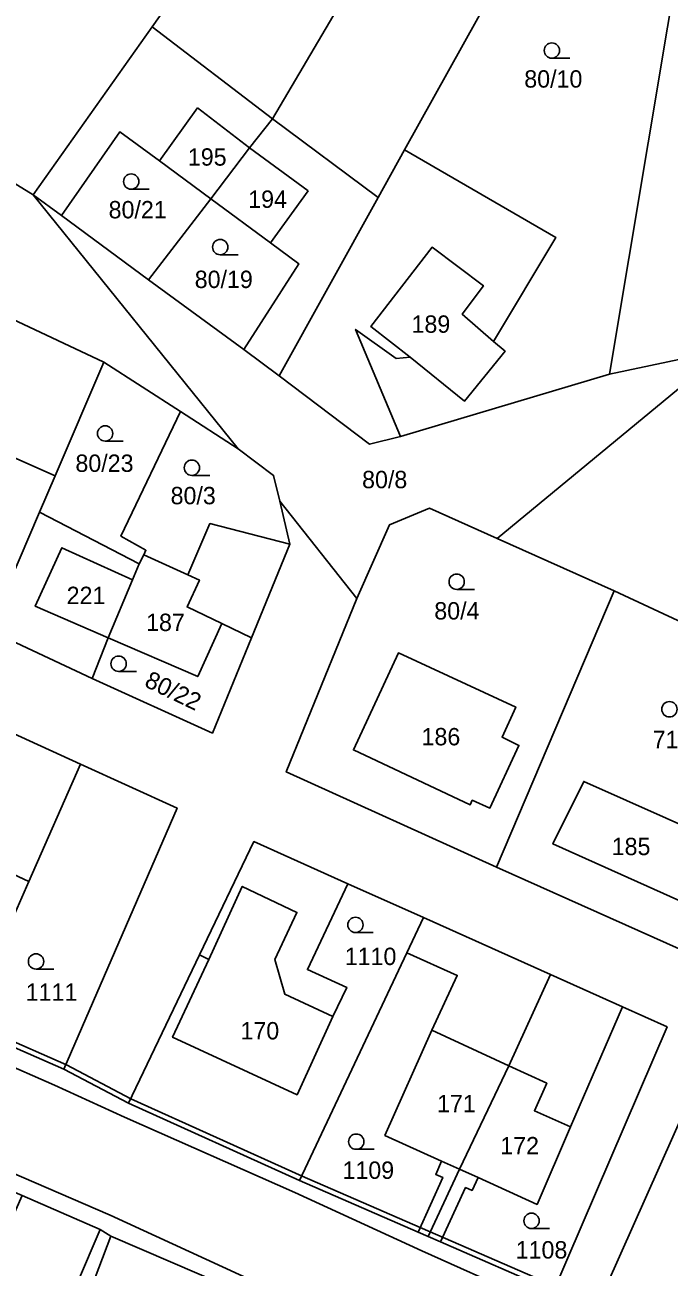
# Model space of a CAD drawing. Extents: x -654083 to -650132, y -1099819 to -1096699.
# Drawn here: x -652413.7 to -652350.7, y -1097932.6 to -1097811 of the extents above; entities that cross this region are included whole.
import ezdxf

# ---------------------------------------------------------------- set-up
doc = ezdxf.new("R2010")
doc.units = 0
for name, color, linetype in [('Hranice - vnitř_ kresba', 7, 'Continuous'), ('Obvody jako plochy', 7, 'Continuous'), ('Ostatní hranice', 7, 'Continuous'), ('Parcelní čísla', 7, 'Continuous'), ('Značky kultur', 7, 'Continuous')]:
    doc.layers.add(name, color=color, linetype=linetype)

msp = doc.modelspace()

# ---------------------------------------------------------------- linework, layer by layer
at = {"layer": 'Hranice - vnitř_ kresba'}
for p, q in [((-652396.84, -1097819.15), (-652400.56, -1097824.34)), ((-652396.84, -1097819.15), (-652391.74, -1097823.07)), ((-652391.74, -1097823.07), (-652385.99, -1097827.27)), ((-652385.99, -1097827.27), (-652389.69, -1097832.37)), ((-652379.85, -1097840.57), (-652373.87, -1097832.79)), ((-652373.87, -1097832.79), (-652368.84, -1097836.57)), ((-652368.84, -1097836.57), (-652370.92, -1097839.35)), ((-652367.85, -1097842.01), (-652370.92, -1097839.35)), ((-652379.85, -1097840.57), (-652376.02, -1097843.57)), ((-652410.12, -1097862.22), (-652412.72, -1097867.95)), ((-652403.2, -1097865.36), (-652410.12, -1097862.22)), ((-652397.78, -1097864.87), (-652396.65, -1097865.38)), ((-652397.86, -1097868.01), (-652396.65, -1097865.38)), ((-652405.57, -1097871.02), (-652412.72, -1097867.95)), ((-652394.46, -1097869.62), (-652397.86, -1097868.01)), ((-652484.26, -1097882.64), (-652410.83, -1097914.82)), ((-652420.25, -1097891.7), (-652413.35, -1097894.89)), ((-652395.73, -1097902.54), (-652392.46, -1097895.37)), ((-652392.46, -1097895.37), (-652387.1, -1097897.91)), ((-652387.1, -1097897.91), (-652389.26, -1097902.54)), ((-652389.26, -1097902.54), (-652388.3, -1097905.93)), ((-652456.16, -1097905.72), (-652405.39, -1097927.55)), ((-652383.59, -1097908.1), (-652388.3, -1097905.93)), ((-652373.9, -1097909.44), (-652366.35, -1097912.94)), ((-652366.35, -1097912.94), (-652362.64, -1097914.64)), ((-652410.83, -1097914.82), (-652404, -1097917.96)), ((-652362.64, -1097914.64), (-652363.85, -1097917.34)), ((-652404, -1097917.96), (-652387.32, -1097925.33)), ((-652363.85, -1097917.34), (-652360.31, -1097918.91)), ((-652372.96, -1097922.26), (-652371.17, -1097923.05)), ((-652371.17, -1097923.05), (-652369.36, -1097923.86)), ((-652387.32, -1097925.33), (-652374.88, -1097931.06)), ((-652405.39, -1097927.55), (-652368.53, -1097944.47)), ((-652374.88, -1097931.06), (-652362.67, -1097936.49))]:
    msp.add_line(p, q, dxfattribs=at)
at = {"layer": 'Obvody jako plochy'}
for points in [[(-652839.76, -1097733.97), (-652826.6, -1097739.44), (-652822.57, -1097741.08), (-652707.93, -1097793.49), (-652704.24, -1097795.08), (-652617.25, -1097835.71), (-652588.75, -1097848.74), (-652581.26, -1097852.35), (-652575.63, -1097854.85), (-652550.17, -1097866.18), (-652501.51, -1097887.82), (-652496.71, -1097889.3), (-652483.12, -1097895.45), (-652482.5, -1097895.73), (-652456.7, -1097907.4), (-652446.55, -1097911.8), (-652439.64, -1097914.73), (-652414, -1097925.64), (-652406.37, -1097928.95), (-652405.33, -1097929.6), (-652381.94, -1097939.67)], [(-652259.95, -1097978.53), (-652289.58, -1097967.54), (-652304.17, -1097961.16), (-652306.89, -1097960.07), (-652358.06, -1097937.32), (-652361.99, -1097934.98), (-652373.04, -1097930.17), (-652374.25, -1097929.65), (-652375.24, -1097929.22), (-652386.86, -1097924.16), (-652403.6, -1097916.6), (-652409.91, -1097913.27), (-652436.78, -1097901.48), (-652463.96, -1097889.56), (-652483.6, -1097880.94), (-652534, -1097858.11), (-652537.59, -1097856.5), (-652554.49, -1097848.9), (-652581.83, -1097835.42), (-652676.84, -1097793.83), (-652695.77, -1097785.5), (-652811.07, -1097733.73)], [(-652500.72, -1097835.3), (-652484.26, -1097848.66), (-652475.91, -1097843.07), (-652447.26, -1097856.27), (-652431.98, -1097863.57), (-652417.27, -1097870.27), (-652407.16, -1097875.02), (-652395.37, -1097880.36), (-652391.55, -1097871.03), (-652387.8, -1097861.86), (-652388.79, -1097857.67), (-652381.25, -1097867.2), (-652388.15, -1097884.17), (-652367.56, -1097893.5), (-652346.61, -1097902.85)], [(-652334.39, -1097876.52), (-652356.03, -1097866.43), (-652367.48, -1097861.3), (-652345.07, -1097842.82)], [(-652361.99, -1097934.98), (-652350.86, -1097909.12), (-652355.23, -1097907.16), (-652362.28, -1097904), (-652374.72, -1097898.42), (-652382.11, -1097895.11), (-652391.32, -1097890.98), (-652396.64, -1097902.08), (-652403.6, -1097916.6), (-652409.91, -1097913.27), (-652398.84, -1097887.71), (-652408.29, -1097883.4), (-652415.21, -1097880.24), (-652420.04, -1097878.04), (-652425.5, -1097875.55), (-652439.82, -1097869.02), (-652453.31, -1097862.91), (-652458.02, -1097860.78), (-652472.61, -1097854.18), (-652477.46, -1097866.14), (-652483.6, -1097880.94), (-652534, -1097858.11)], [(-652346.41, -1097911.18), (-652358.06, -1097937.32)]]:
    msp.add_lwpolyline(points, dxfattribs=at)
for points in [[(-652379.48, -1097780.45), (-652401.26, -1097811.21), (-652412.92, -1097827.67), (-652420.53, -1097823), (-652433.6, -1097806.15), (-652430.36, -1097800.91), (-652417.6, -1097810.84), (-652413.9, -1097806.33), (-652416.04, -1097804.59), (-652414.87, -1097802.5), (-652417.21, -1097800.53), (-652415.53, -1097798.38), (-652418.34, -1097796.15), (-652417.34, -1097794.99), (-652420.39, -1097792.61), (-652419.7, -1097791.77), (-652421.1, -1097790.74), (-652426.06, -1097786.86), (-652405.32, -1097768.69), (-652381.57, -1097778.69)], [(-652370.5, -1097787.99), (-652389.49, -1097820.24), (-652401.26, -1097811.21), (-652379.48, -1097780.45)], [(-652376.56, -1097823.27), (-652360.94, -1097795.15), (-652370.5, -1097787.99), (-652389.49, -1097820.24), (-652379.15, -1097827.93)], [(-652348.92, -1097799.91), (-652356.49, -1097845.22), (-652376.96, -1097851.32), (-652381.36, -1097840.85), (-652377.38, -1097843.7), (-652376.02, -1097843.57), (-652370.69, -1097847.86), (-652366.72, -1097842.98), (-652367.85, -1097842.01), (-652361.76, -1097831.84), (-652376.56, -1097823.27), (-652360.94, -1097795.15)], [(-652345.07, -1097842.82), (-652333.27, -1097839.84), (-652323.69, -1097812.92), (-652334.65, -1097806.31), (-652348.92, -1097799.91), (-652356.49, -1097845.22)], [(-652398.51, -1097848.89), (-652406, -1097844.06), (-652419.57, -1097837.69), (-652435.51, -1097803.7), (-652433.6, -1097806.15), (-652420.53, -1097823), (-652412.92, -1097827.67), (-652392.87, -1097852.52)], [(-652389.49, -1097820.24), (-652401.26, -1097811.21), (-652412.92, -1097827.67), (-652410.15, -1097829.7), (-652404.43, -1097821.49), (-652400.56, -1097824.34), (-652395.54, -1097828.05), (-652391.74, -1097823.07)], [(-652396.84, -1097819.15), (-652391.74, -1097823.07), (-652395.54, -1097828.05), (-652400.56, -1097824.34)], [(-652389.49, -1097820.24), (-652379.15, -1097827.93), (-652388.83, -1097845.37), (-652392.3, -1097842.8), (-652386.93, -1097834.41), (-652389.69, -1097832.37), (-652395.54, -1097828.05), (-652391.74, -1097823.07)], [(-652400.56, -1097824.34), (-652404.43, -1097821.49), (-652410.15, -1097829.7), (-652401.62, -1097835.99), (-652395.54, -1097828.05)], [(-652385.99, -1097827.27), (-652389.69, -1097832.37), (-652395.54, -1097828.05), (-652391.74, -1097823.07)], [(-652370.69, -1097847.86), (-652366.72, -1097842.98), (-652367.85, -1097842.01), (-652361.76, -1097831.84), (-652376.56, -1097823.27), (-652379.15, -1097827.93), (-652388.83, -1097845.37), (-652380.01, -1097852.09), (-652376.96, -1097851.32), (-652381.36, -1097840.85), (-652377.38, -1097843.7), (-652376.02, -1097843.57)], [(-652378.03, -1097859.96), (-652381.25, -1097867.2), (-652388.79, -1097857.67), (-652389.39, -1097855.14), (-652392.87, -1097852.52), (-652412.92, -1097827.67), (-652410.15, -1097829.7), (-652401.62, -1097835.99), (-652392.3, -1097842.8), (-652388.83, -1097845.37), (-652380.01, -1097852.09), (-652376.96, -1097851.32), (-652356.49, -1097845.22), (-652345.07, -1097842.82), (-652367.48, -1097861.3), (-652374.12, -1097858.33)], [(-652389.69, -1097832.37), (-652386.93, -1097834.41), (-652392.3, -1097842.8), (-652401.62, -1097835.99), (-652395.54, -1097828.05)], [(-652376.02, -1097843.57), (-652370.69, -1097847.86), (-652366.72, -1097842.98), (-652367.85, -1097842.01), (-652370.92, -1097839.35), (-652368.84, -1097836.57), (-652373.87, -1097832.79), (-652379.85, -1097840.57)], [(-652410.79, -1097855.19), (-652406, -1097844.06), (-652419.57, -1097837.69), (-652421.32, -1097836.9), (-652429.03, -1097841.42), (-652432.79, -1097850.39), (-652435.71, -1097857.37), (-652430.1, -1097859.83), (-652421.88, -1097863.51), (-652416.92, -1097852.46)], [(-652402.1, -1097862.91), (-652402.54, -1097863.79), (-652412.32, -1097858.74), (-652410.79, -1097855.19), (-652406, -1097844.06), (-652398.51, -1097848.89), (-652404.33, -1097861.08), (-652401.88, -1097862.46)], [(-652388.79, -1097857.67), (-652387.8, -1097861.86), (-652395.62, -1097859.85), (-652397.78, -1097864.87), (-652402.1, -1097862.91), (-652401.88, -1097862.46), (-652404.33, -1097861.08), (-652398.51, -1097848.89), (-652392.87, -1097852.52), (-652389.39, -1097855.14)], [(-652412.32, -1097858.74), (-652410.79, -1097855.19), (-652416.92, -1097852.46), (-652421.88, -1097863.51), (-652430.1, -1097859.83), (-652431.98, -1097863.57), (-652417.27, -1097870.27)], [(-652407.16, -1097875.02), (-652405.57, -1097871.02), (-652403.2, -1097865.36), (-652402.54, -1097863.79), (-652412.32, -1097858.74), (-652417.27, -1097870.27)], [(-652356.03, -1097866.43), (-652367.48, -1097861.3), (-652374.12, -1097858.33), (-652378.03, -1097859.96), (-652381.25, -1097867.2), (-652388.15, -1097884.17), (-652367.56, -1097893.5)], [(-652387.8, -1097861.86), (-652391.55, -1097871.03), (-652394.46, -1097869.62), (-652396.82, -1097874.83), (-652405.57, -1097871.02), (-652403.2, -1097865.36), (-652402.54, -1097863.79), (-652402.1, -1097862.91), (-652397.78, -1097864.87), (-652395.62, -1097859.85)], [(-652403.2, -1097865.36), (-652405.57, -1097871.02), (-652412.72, -1097867.95), (-652410.12, -1097862.22)], [(-652396.82, -1097874.83), (-652394.46, -1097869.62), (-652397.86, -1097868.01), (-652396.65, -1097865.38), (-652397.78, -1097864.87), (-652402.1, -1097862.91), (-652402.54, -1097863.79), (-652403.2, -1097865.36), (-652405.57, -1097871.02)], [(-652334.39, -1097876.52), (-652356.03, -1097866.43), (-652367.56, -1097893.5), (-652346.61, -1097902.85)], [(-652395.37, -1097880.36), (-652407.16, -1097875.02), (-652405.57, -1097871.02), (-652396.82, -1097874.83), (-652394.46, -1097869.62), (-652391.55, -1097871.03)], [(-652381.57, -1097882.01), (-652370.15, -1097887.39), (-652369.93, -1097886.94), (-652368.21, -1097887.7), (-652365.37, -1097881.57), (-652367.02, -1097880.76), (-652365.68, -1097877.82), (-652377.16, -1097872.52)], [(-652365.68, -1097877.82), (-652377.16, -1097872.52), (-652381.57, -1097882.01), (-652370.15, -1097887.39), (-652369.93, -1097886.94), (-652368.21, -1097887.7), (-652365.37, -1097881.57), (-652367.02, -1097880.76)], [(-652381.57, -1097882.01), (-652370.15, -1097887.39), (-652369.93, -1097886.94), (-652368.21, -1097887.7), (-652365.37, -1097881.57), (-652367.02, -1097880.76), (-652365.68, -1097877.82), (-652377.16, -1097872.52)], [(-652425.5, -1097875.55), (-652420.04, -1097878.04), (-652420.86, -1097879.73), (-652423.86, -1097878.35), (-652430.97, -1097895.54), (-652416.57, -1097902.2), (-652413.35, -1097894.89), (-652408.29, -1097883.4), (-652398.84, -1097887.71), (-652409.91, -1097913.27), (-652436.78, -1097901.48)], [(-652420.86, -1097879.73), (-652420.04, -1097878.04), (-652415.21, -1097880.24), (-652408.29, -1097883.4), (-652413.35, -1097894.89), (-652416.57, -1097902.2), (-652430.97, -1097895.54), (-652423.86, -1097878.35)], [(-652420.86, -1097879.73), (-652420.04, -1097878.04), (-652415.21, -1097880.24), (-652420.25, -1097891.7), (-652413.35, -1097894.89), (-652416.57, -1097902.2), (-652430.97, -1097895.54), (-652423.86, -1097878.35)], [(-652346.76, -1097890.55), (-652359.02, -1097885.1), (-652362.03, -1097891.21), (-652349.61, -1097896.78)], [(-652359.02, -1097885.1), (-652362.03, -1097891.21), (-652349.61, -1097896.78), (-652346.76, -1097890.55)], [(-652362.03, -1097891.21), (-652349.61, -1097896.78), (-652346.76, -1097890.55), (-652359.02, -1097885.1)], [(-652395.73, -1097902.54), (-652399.27, -1097910.14), (-652387.08, -1097915.77), (-652383.59, -1097908.1), (-652382.23, -1097905.26), (-652386.07, -1097903.51), (-652382.11, -1097895.11), (-652391.32, -1097890.98), (-652396.64, -1097902.08)], [(-652376.35, -1097901.87), (-652374.72, -1097898.42), (-652382.11, -1097895.11), (-652386.07, -1097903.51), (-652382.23, -1097905.26), (-652383.59, -1097908.1), (-652387.08, -1097915.77), (-652399.27, -1097910.14), (-652395.73, -1097902.54), (-652396.64, -1097902.08), (-652403.6, -1097916.6), (-652386.86, -1097924.16)], [(-652395.73, -1097902.54), (-652399.27, -1097910.14), (-652387.08, -1097915.77), (-652383.59, -1097908.1), (-652388.3, -1097905.93), (-652389.26, -1097902.54), (-652387.1, -1097897.91), (-652392.46, -1097895.37)], [(-652366.35, -1097912.94), (-652371.17, -1097923.05), (-652374.25, -1097929.65), (-652375.24, -1097929.22), (-652372.83, -1097923.86), (-652373.5, -1097923.56), (-652372.96, -1097922.26), (-652378.49, -1097919.75), (-652373.9, -1097909.44), (-652371.4, -1097904.08), (-652376.35, -1097901.87), (-652374.72, -1097898.42), (-652362.28, -1097904)], [(-652386.86, -1097924.16), (-652376.35, -1097901.87), (-652371.4, -1097904.08), (-652373.9, -1097909.44), (-652378.49, -1097919.75), (-652372.96, -1097922.26), (-652373.5, -1097923.56), (-652372.83, -1097923.86), (-652375.24, -1097929.22)], [(-652360.31, -1097918.91), (-652363.59, -1097926.5), (-652369.36, -1097923.86), (-652369.95, -1097925.13), (-652370.58, -1097924.86), (-652373.04, -1097930.17), (-652374.25, -1097929.65), (-652371.17, -1097923.05), (-652366.35, -1097912.94), (-652362.28, -1097904), (-652355.23, -1097907.16)], [(-652355.23, -1097907.16), (-652350.86, -1097909.12), (-652361.99, -1097934.98), (-652373.04, -1097930.17), (-652370.58, -1097924.86), (-652369.95, -1097925.13), (-652369.36, -1097923.86), (-652363.59, -1097926.5), (-652360.31, -1097918.91)], [(-652373.9, -1097909.44), (-652366.35, -1097912.94), (-652371.17, -1097923.05), (-652372.96, -1097922.26), (-652378.49, -1097919.75)], [(-652306.95, -1097957.89), (-652303.66, -1097959.19), (-652304.17, -1097961.16), (-652306.89, -1097960.07), (-652358.06, -1097937.32), (-652346.41, -1097911.18), (-652296.09, -1097929.62), (-652301.21, -1097949.62), (-652303.07, -1097948.9)], [(-652366.35, -1097912.94), (-652371.17, -1097923.05), (-652369.36, -1097923.86), (-652363.59, -1097926.5), (-652360.31, -1097918.91), (-652363.85, -1097917.34), (-652362.64, -1097914.64)], [(-652406.37, -1097928.95), (-652441.31, -1098010.62), (-652447.9, -1098029.02), (-652446.63, -1098037.02), (-652449.67, -1098045.65), (-652448.23, -1098058.23), (-652448.88, -1098063.04), (-652447.64, -1098063.77), (-652446.77, -1098071.83), (-652437.07, -1098091.68), (-652437.83, -1098101.1), (-652440.05, -1098093.64), (-652454.71, -1098064.74), (-652452.31, -1098042.44), (-652453.12, -1098030.34), (-652446.61, -1098008.03), (-652438.33, -1097987.15), (-652440.24, -1097986.29), (-652429.99, -1097961.76), (-652414, -1097925.64)], [(-652405.33, -1097929.6), (-652422.68, -1097975.33), (-652437.49, -1098013.22), (-652439.91, -1098012.57), (-652445.26, -1098033.11), (-652446.63, -1098037.02), (-652447.9, -1098029.02), (-652441.31, -1098010.62), (-652406.37, -1097928.95)], [(-652384.83, -1097946.54), (-652381.94, -1097939.67), (-652405.33, -1097929.6), (-652422.68, -1097975.33), (-652415.19, -1097978.98), (-652395.13, -1097968.29), (-652393.87, -1097966.93), (-652396.26, -1097965.83), (-652393.29, -1097959.44), (-652390.51, -1097953.39), (-652387.9, -1097954.68)]]:
    msp.add_lwpolyline(points, close=True, dxfattribs=at)
at = {"layer": 'Ostatní hranice'}
for p, q in [((-652436.51, -1097901.06), (-652409.68, -1097912.83)), ((-652409.68, -1097912.83), (-652403.37, -1097916.16)), ((-652403.37, -1097916.16), (-652386.6, -1097923.73)), ((-652386.6, -1097923.73), (-652361.76, -1097934.54))]:
    msp.add_line(p, q, dxfattribs=at)
at = {"layer": 'Značky kultur'}
for p, q in [((-652360.39, -1097814.29), (-652362.14, -1097814.29)), ((-652401.58, -1097827.12), (-652403.33, -1097827.12)), ((-652392.86, -1097833.53), (-652394.61, -1097833.53)), ((-652404.13, -1097851.78), (-652405.88, -1097851.78)), ((-652395.64, -1097855.13), (-652397.39, -1097855.13)), ((-652369.71, -1097866.29), (-652371.46, -1097866.29)), ((-652402.81, -1097874.32), (-652404.56, -1097874.32)), ((-652379.62, -1097899.89), (-652381.37, -1097899.89)), ((-652410.9, -1097903.47), (-652412.65, -1097903.47)), ((-652379.54, -1097921.11), (-652381.29, -1097921.11)), ((-652362.38, -1097928.86), (-652364.13, -1097928.86))]:
    msp.add_line(p, q, dxfattribs=at)
for centre in [(-652362.14, -1097813.54), (-652403.33, -1097826.37), (-652394.61, -1097832.78), (-652405.88, -1097851.03), (-652397.39, -1097854.38), (-652371.46, -1097865.54), (-652404.56, -1097873.57), (-652350.63, -1097878.03), (-652381.37, -1097899.14), (-652412.65, -1097902.72), (-652381.29, -1097920.36), (-652364.13, -1097928.11)]:
    msp.add_circle(centre, 0.75, dxfattribs=at)

# ---------------------------------------------------------------- texts
at = {"layer": 'Parcelní čísla'}
for s, p in [('80/10', (-652364.84, -1097817.17)), ('195', (-652397.78, -1097824.81)), ('194', (-652391.87, -1097828.94)), ('80/21', (-652405.54, -1097829.97)), ('80/19', (-652397.11, -1097836.79)), ('189', (-652375.88, -1097841.17)), ('80/23', (-652408.79, -1097854.79)), ('80/8', (-652380.72, -1097856.39)), ('80/3', (-652399.47, -1097857.96)), ('221', (-652409.65, -1097867.73)), ('80/4', (-652373.65, -1097869.24)), ('187', (-652401.87, -1097870.37)), ('186', (-652374.9, -1097881.56)), ('71/2', (-652352.27, -1097881.84)), ('185', (-652356.28, -1097892.31)), ('1110', (-652382.42, -1097903.07)), ('1111', (-652413.66, -1097906.57)), ('170', (-652392.63, -1097910.35)), ('171', (-652373.38, -1097917.48)), ('172', (-652367.19, -1097921.6)), ('1109', (-652382.64, -1097924)), ('1108', (-652365.68, -1097931.8))]:
    msp.add_text(s, height=1.7, dxfattribs=at).set_placement(p)
msp.add_text('80/22', height=1.7, rotation=334.251, dxfattribs=at).set_placement((-652402.14, -1097875.74))

doc.saveas('drawing.dxf')
